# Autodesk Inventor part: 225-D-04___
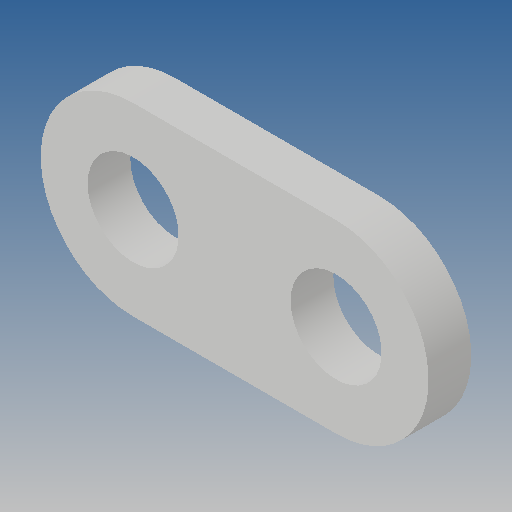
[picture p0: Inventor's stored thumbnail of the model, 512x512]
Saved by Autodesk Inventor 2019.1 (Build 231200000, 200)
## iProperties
Created: 2013-01
Part Number: 225-D-04___
Material: Ogólny
Document SubType Name: Modeling
Designer: CADENGINEERING4
Density: 1 g/cm^3
Appearance: Domyślna
Author: CADENGINEERING4
Revision Number: ÈÎºÎ
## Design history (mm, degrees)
feature "NONE"
node "Bryła1"
